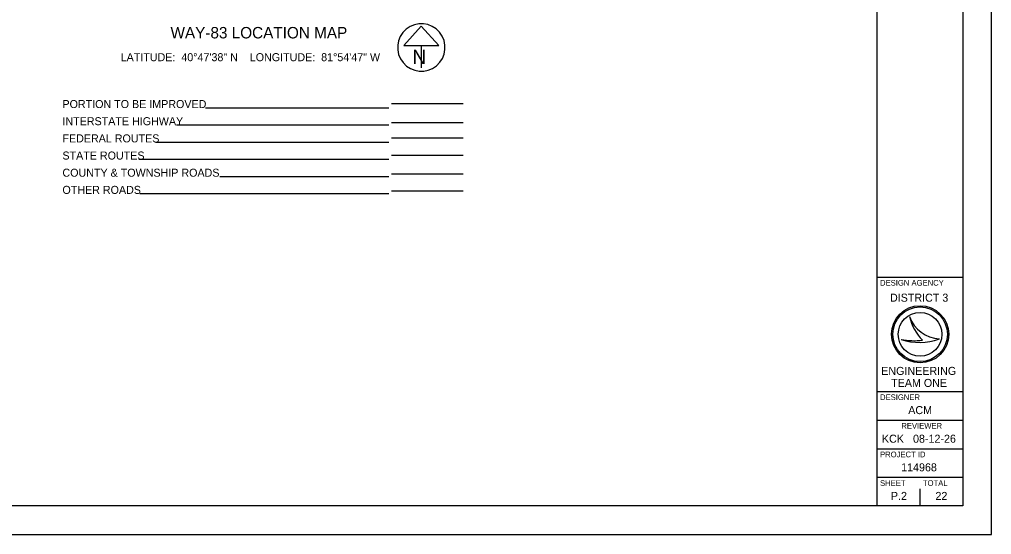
# Model space of a CAD drawing. Extents: x 0 to 34, y 0 to 22.
# Drawn here: x 17 to 34, y 0 to 9 of the extents above; entities that cross this region are included whole.
import ezdxf

# ---------------------------------------------------------------- set-up
doc = ezdxf.new("R2010")
doc.units = 0
for name, color, linetype in [('SH_Border', 7, 'Continuous'), ('SH_Cut_Line', 7, 'Continuous'), ('SH_Data', 7, 'Continuous'), ('SH_Text', 7, 'Continuous')]:
    doc.layers.add(name, color=color, linetype=linetype)

msp = doc.modelspace()

# ---------------------------------------------------------------- linework, layer by layer
at = {"layer": 'SH_Border'}
for p, q in [((32, 0.5), (32, 21.5)), ((32, 4.5), (33.5, 4.5)), ((32, 2.5), (33.5, 2.5)), ((32, 2), (33.5, 2)), ((32, 1.5), (33.5, 1.5)), ((32, 1), (33.5, 1))]:
    msp.add_line(p, q, dxfattribs=at)
msp.add_lwpolyline([(1.5, 21.5), (33.5, 21.5), (33.5, 0.5), (1.5, 0.5)], close=True, dxfattribs=at)
at = {"layer": 'SH_Cut_Line'}
msp.add_lwpolyline([(0, 0), (34, 0), (34, 22), (0, 22)], close=True, dxfattribs=at)
at = {"layer": 'SH_Data'}
for p, q in [((24.028, 8.887), (23.72, 8.545)), ((24.335, 8.545), (24.028, 8.887)), ((23.72, 8.545), (24.335, 8.545)), ((24.028, 8.545), (24.028, 8.159)), ((24.028, 8.513), (24.028, 8.513)), ((24.028, 8.513), (24.028, 8.513)), ((23.508, 7.533), (24.758, 7.533)), ((23.458, 7.454), (20.252, 7.454)), ((23.458, 7.154), (19.747, 7.154)), ((24.758, 7.198), (23.508, 7.198)), ((23.458, 6.854), (19.377, 6.854)), ((24.758, 6.927), (23.508, 6.927)), ((23.458, 6.554), (19.087, 6.554)), ((24.758, 6.627), (23.508, 6.627)), ((24.758, 6.3), (23.508, 6.3)), ((23.458, 6.254), (20.503, 6.254)), ((23.458, 5.954), (19.105, 5.954)), ((24.758, 6), (23.508, 6)), ((32.567, 3.81), (32.567, 3.81)), ((32.417, 3.41), (32.417, 3.41)), ((32.75, 3.5), (32.75, 3.5)), ((33.087, 3.419), (33.087, 3.419)), ((32.75, 0.5), (32.75, 0.8)), ((32.375, 0.675), (32.375, 0.675))]:
    msp.add_line(p, q, dxfattribs=at)
for radius in [0.5, 0.477, 0.477, 0.382]:
    msp.add_circle((32.75, 3.5), radius, dxfattribs=at)
for centre, radius, start, end in [((24.028, 8.513), 0.415, 129.7798, 129.7633), ((33.116, 3.998), 0.58, 198.9257, 198.9319), ((33.347, 3.97), 0.796, 191.6379, 191.6421), ((33.116, 3.998), 0.58, 198.9319, 267.1657), ((33.347, 3.97), 0.796, 191.6421, 226.0947), ((32.739, 4.37), 1.013, 251.4576, 290.0832), ((32.648, 4.654), 1.266, 259.4964, 259.4995), ((32.739, 4.37), 1.013, 251.4527, 251.4576), ((32.648, 4.654), 1.266, 259.4995, 276.6672)]:
    msp.add_arc(centre, radius, start, end, dxfattribs=at)

# ---------------------------------------------------------------- texts
for s, height, p in [('N', 0.25, (23.872, 8.222)), ('DESIGN AGENCY', 0.1, (32.05, 4.35)), ('DISTRICT 3', 0.14, (32.224, 4.07)), ('ENGINEERING', 0.14, (32.071, 2.79)), ('TEAM ONE', 0.14, (32.244, 2.58)), ('DESIGNER', 0.1, (32.05, 2.35)), ('ACM', 0.14, (32.543, 2.105)), ('REVIEWER', 0.1, (32.422, 1.85)), ('KCK', 0.14, (32.083, 1.605)), ('08-12-26', 0.14, (32.627, 1.605)), ('PROJECT ID', 0.1, (32.05, 1.35)), ('114968', 0.14, (32.419, 1.105)), ('SHEET', 0.1, (32.05, 0.85)), ('TOTAL', 0.1, (32.8, 0.85)), ('P.2', 0.14, (32.24, 0.605)), ('22', 0.14, (33.019, 0.605))]:
    msp.add_text(s, height=height, dxfattribs=at).set_placement(p)
at = {"layer": 'SH_Text'}
for s, height, p in [('WAY-83 LOCATION MAP', 0.2, (19.642, 8.671)), ('LATITUDE:  40°47\'38" N    LONGITUDE:  81°54\'47" W', 0.14, (18.77, 8.273)), ('PORTION TO BE IMPROVED', 0.14, (17.752, 7.454)), ('INTERSTATE HIGHWAY', 0.14, (17.752, 7.154)), ('FEDERAL ROUTES', 0.14, (17.752, 6.854)), ('STATE ROUTES', 0.14, (17.752, 6.554)), ('COUNTY & TOWNSHIP ROADS', 0.14, (17.752, 6.254)), ('OTHER ROADS', 0.14, (17.752, 5.954))]:
    msp.add_text(s, height=height, dxfattribs=at).set_placement(p)

doc.saveas('drawing.dxf')
